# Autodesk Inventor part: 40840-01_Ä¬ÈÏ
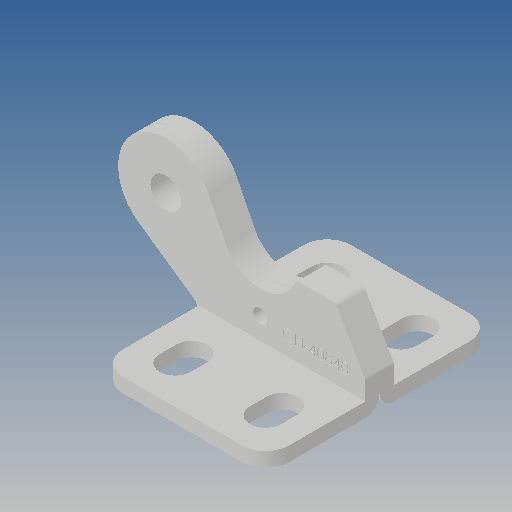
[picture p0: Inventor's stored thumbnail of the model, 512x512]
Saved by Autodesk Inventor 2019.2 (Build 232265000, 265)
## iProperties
Created: 2010-06
Part Number: 40840-01_Ä¬ÈÏ
Material: Ogólny
Document SubType Name: Modeling
Designer: CADENGINEERING4
Density: 1 g/cm^3
Appearance: Domyślna
Author: CADENGINEERING4
Revision Number: ÈÎºÎ
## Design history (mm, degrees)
feature "NONE"
feature "NONE:1"
node "Bryła1"
node "Bryła2"
